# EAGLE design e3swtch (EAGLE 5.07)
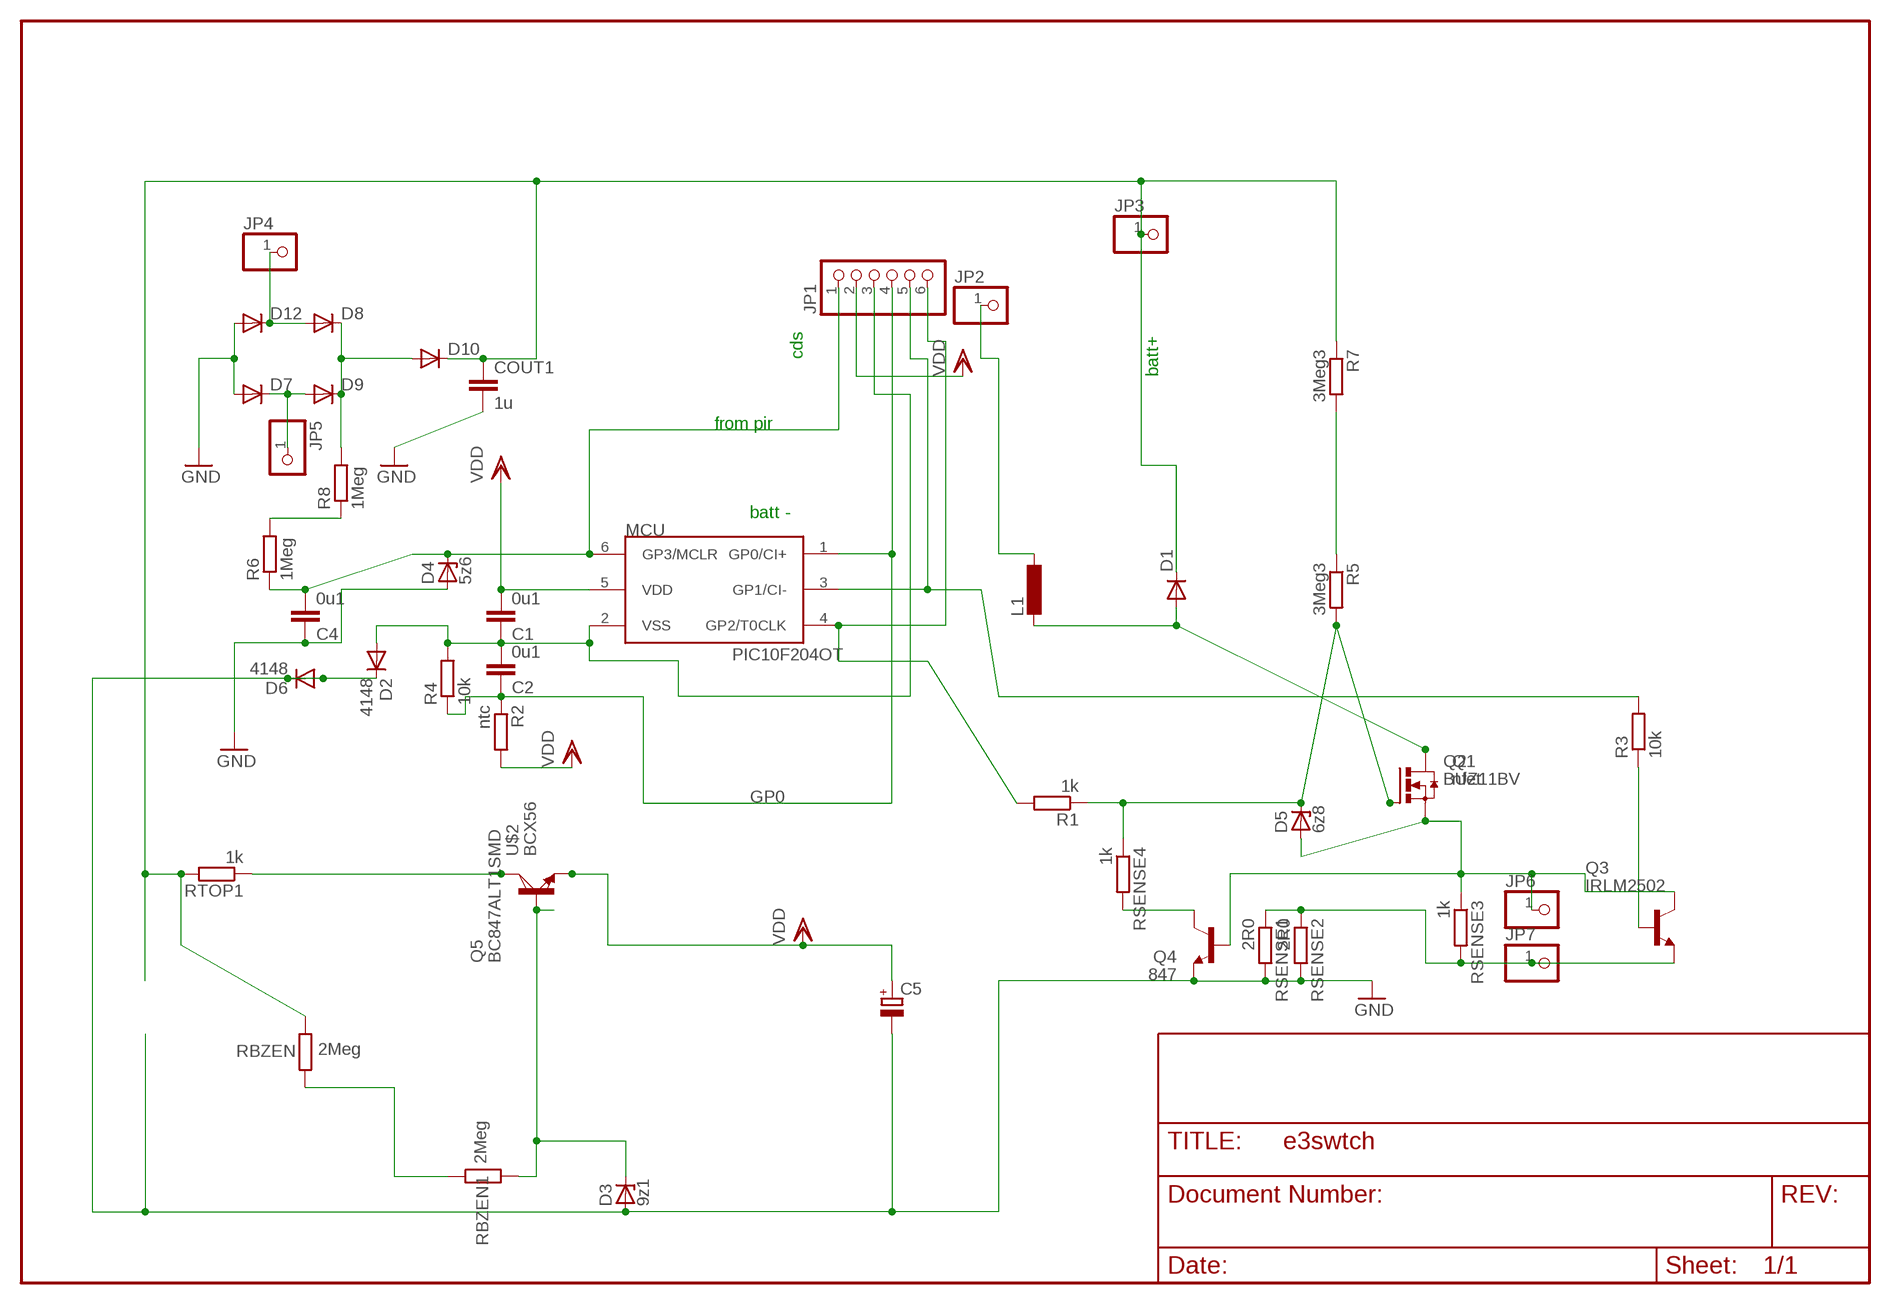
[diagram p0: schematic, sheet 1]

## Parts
C1  0u1  C-EUC0805  [C0805]
C2  0u1  C-EUC0805  [C0805]
C4  0u1  C-EUC1206  [C1206]
C5  CPOL-EUSANYO_SMD_C6  [SANYO-OSCON_SMD_C6]
COUT1  1u  C-EU075-032X103  [C075-032X103]
D1  DIODE-SMC  [SMC]
D2  4148  1N4148MINIMELF  [MINIMELF]
D3  9z1  ZENER-DIODESOD80C  [SOD80C]
D4  5z6  ZENER-DIODESOD80C  [SOD80C]
D5  6z8  ZENER-DIODESOD80C  [SOD80C]
D6  4148  1N4148MINIMELF  [MINIMELF]
D7  DIODE-DO214AA  [DO214AA]
D8  DIODE-SOD80C  [SOD80C]
D9  DIODE-SOD80C  [SOD80C]
D10  DIODE-SOD80C  [SOD80C]
D12  DIODE-DO214AA  [DO214AA]
JP1  PINHD-1X6  [1X06BOX]
JP2  PINHD-1X11MM6  [1X1MM8]
JP3  PINHD-1X11MM6  [1X1MM8]
JP4  PINHD-1X11MM6  [1X1MM8]
JP5  PINHD-1X11MM6  [1X1MM8]
JP6  PINHD-1X1INCH  [1X01]
JP7  PINHD-1X1INCH  [1X01]
L1  L-EUPIS2816  [PIS2816]
MCU  PIC10F204OT  [SOT23-6]
Q1  nfet  N-HEXFET_DPAK-  [TO252]
Q2  BUZ11BV  [TO220BV]
Q3  IRLM2502  BC847ALT1SMD  [SOT23]
Q4  847  BC847ASMD  [SOT23]
Q5  BC847ALT1SMD  [SOT23]
R1  1k  R-EU_R0805  [R0805]
R2  ntc  R-EU_0204/5  [0204/5]
R3  10k  R-EU_R0805  [R0805]
R4  10k  R-EU_R0805  [R0805]
R5  3Meg3  R-EU_R1206  [R1206]
R6  1Meg  R-EU_R1206  [R1206]
R7  3Meg3  R-EU_R1206  [R1206]
R8  1Meg  R-EU_R1206  [R1206]
RBZEN  2Meg  R-EU_R1206  [R1206]
RBZEN1  2Meg  R-EU_R1206  [R1206]
RSENSE1  2R0  R-EU_R1210  [R1210]
RSENSE2  2R0  R-EU_R1206  [R1206]
RSENSE3  1k  R-EU_R1206  [R1206]
RSENSE4  1k  R-EU_0204/5  [0204/5]
RTOP1  1k  R-EU_R1206  [R1206]
U$2  BCX56  [SOT223]

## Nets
AC1: D8.A D12.C JP4.1
AC2: D7.C D9.A JP5.1
BSW1: JP7.1 Q3.2(E) RSENSE1.1 RSENSE2.1 RSENSE3.2
C: Q5.3(C) RTOP1.1 U$2.2(C)
CB: D3.C Q5.1(B) RBZEN1.2 U$2.1(B)
GND: C4.1 C5.- COUT1.2 D2.C D3.A D4.A D6.A D6.C D7.A D12.A Q4.2(E) RSENSE1.2 RSENSE2.2
GP0: C2.1 JP1.4 MCU.1(GP0/CI+) R2.1 R4.1
HOT: D1.A L1.2 Q1.3(D) Q2.D
LED-: JP2.1 L1.1
N$1: D5.C Q1.1(G) Q2.G R1.1 R5.2 RSENSE4.1
N$3: C4.2 D4.C JP1.1 MCU.6(GP3/MCLR) R6.1
N$4: R5.1 R7.2
N$5: Q3.1(B) R3.1
N$6: RBZEN1.1 RBZEN.2
N$7: Q4.3(C) RSENSE4.2
N$9: R6.2 R8.1
N$12: JP1.5 MCU.3(GP1/CI-) R3.2
N$14: JP1.6 MCU.4(GP2/T0CLK) R1.2
N$16: D8.C D9.C D10.A R8.2
S: D5.A JP6.1 Q1.2(S) Q2.S Q3.3(C) Q4.1(B) RSENSE3.1
VDD: C1.2 C5.+ JP1.2 MCU.5(VDD) Q5.2(E) R2.2 U$2.3(E)
VPLUS: COUT1.1 D1.C D10.C JP3.1 R7.1 RBZEN.1 RTOP1.2
VSS: C1.1 C2.2 D2.A JP1.3 MCU.2(VSS) R4.2

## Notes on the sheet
- cds
- batt+
- from pir
- batt -

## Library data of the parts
C1 C2 C4 COUT1 = rcl:C-EU: CAPACITOR, European symbol
C5 = rcl-2:CPOL-EU: POLARIZED CAPACITOR, European symbol
D1 = diode-1:DIODE-: DIODE
D2 D6 = diode-1:1N4148: DIODE
D3-D5 = diode:ZENER-DIODE: Z-Diode
D7-D10 D12 = diode:DIODE-: DIODE
JP1 = pinhead:PINHD-1X6: PIN HEADER
JP2-JP5 = pinhead:PINHD-1X1: PIN HEADER
JP6 JP7 = pinhead(2):PINHD-1X1: PIN HEADER
L1 = rcl:L-EU: INDUCTOR, European symbol
MCU = microchip-3:PIC10F2*: uPC nW 0,25/0,5k Program Flash memory Comparator
Q1 = transistor-power:N-HEXFET_?-*: HEXFET® Power MOSFET
Q2 = transistor-power:BUZ11: N-CHANNEL MOS FET
Q3-Q5 = transistor-npn:BC847*: NPN Transistor
R1-R3 R5 R7 RBZEN RBZEN1 RSENSE1-RSENSE4 RTOP1 = rcl:R-EU_: RESISTOR, European symbol
R4 R6 R8 = rcl-2:R-EU_: RESISTOR, European symbol
U$2 = transistor-power:BCX56

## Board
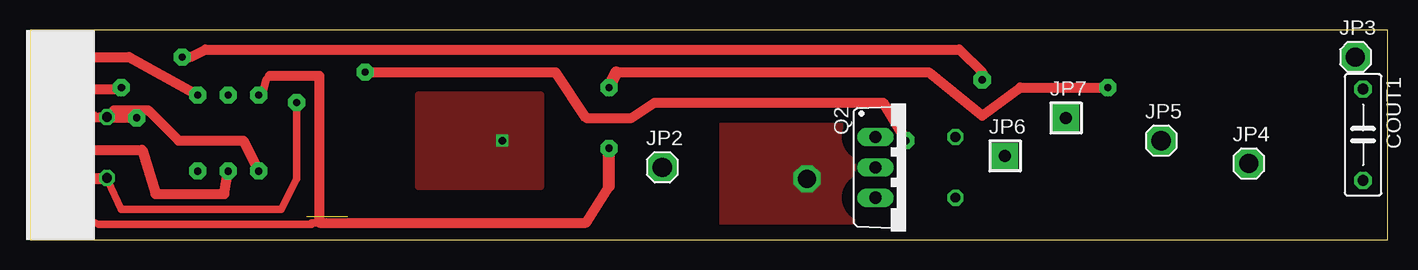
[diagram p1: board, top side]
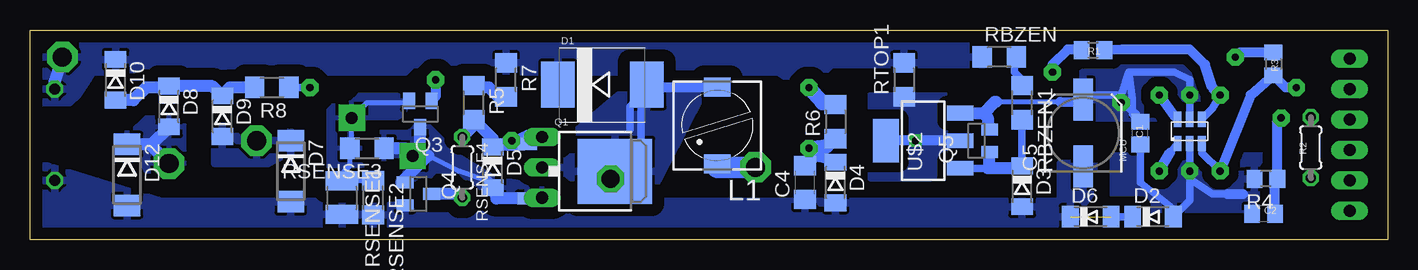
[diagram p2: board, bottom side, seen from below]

Size 113.19 x 17.5 mm. Coordinates in mm from the lower left corner, seen from the top.
Outline: 0,0 113.19,0 113.19,17.5 0,17.5 0,0
Copper layers (1*16): Top 0.035mm / dielectric 1.5mm / Bottom 0.035mm
Design rules "default *": minimum track width 10mil, minimum drill 24mil, track to track 8mil, track to pad 8mil, pad to pad 8mil, via to via 8mil, smd to smd 8mil, copper to edge 20mil, drill to drill 8mil, minimum pad ring 10mil, minimum via ring 8mil, stop-mask expansion 4mil, vias tented up to drill 0mil, thermal gap 10mil

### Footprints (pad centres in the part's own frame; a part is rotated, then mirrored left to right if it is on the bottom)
C0805 = smd 1.3 x 1.5: 1 -0.95,0; 2 0.95,0
C1206 = smd 1.6 x 1.8: 1 -1.4,0; 2 1.4,0
SANYO-OSCON_SMD_C6 = smd 3.5 x 1.6: + 2.8,0; - -2.8,0
C075-032X103 = drill 0.914 octagon: 1 -3.81,0; 2 3.81,0
SMC = smd 2.8 x 3.8: A 3.7,0; C -3.7,0
MINIMELF = smd 1.4 x 1.8: A 1.7,0; C -1.7,0
SOD80C = smd 1.4 x 1.8: A 1.7,0; C -1.7,0
DO214AA = smd 1.8 x 2.2: A 2.55,0; C -2.55,0
1X06BOX = drill 1.016 long: 1 -6.35,0; 2 -3.81,0; 3 -1.27,0; 4 1.27,0; 5 3.81,0; 6 6.35,0
1X1MM8 = drill 1.6 pad 2.54 octagon: 1 0,0
1X01 = drill 1 pad 2.184 square: 1 0,0
PIS2816 = smd 2.2 x 1.6: 1 0,3.2; 2 0,-3.2
SOT23-6 = smd 0.635 x 1.27: 1 -1.016,-1.016; 2 0,-1.016; 3 1.016,-1.016; 4 1.016,1.016; 5 0,1.016; 6 -1.016,1.016
TO252 = smd 1 x 1.6: 1 -2.28,-3.53; 2 2.28,-3.53 | smd 5.4 x 6.2: 3 0,3.77
TO220BV = drill 1.016 long: D 0,-2.54; G -2.54,-2.54; S 2.54,-2.54
SOT23 = smd 1 x 1.4: 1 -0.95,-1.1; 2 0.95,-1.1; 3 0,1.1
R0805 = smd 1.3 x 1.5: 1 -0.95,0; 2 0.95,0
0204/5 = drill 0.813 octagon: 1 -2.54,0; 2 2.54,0
R1206 = smd 1.6 x 1.803: 1 -1.422,0; 2 1.422,0
R1210 = smd 1.6 x 2.7: 1 -1.4,0; 2 1.4,0
SOT223 = smd 1.219 x 2.235: 1 -2.311,-3.099; 2 0,-3.099; 3 2.311,-3.099 | smd 3.6 x 2.2: 4 0,3.099

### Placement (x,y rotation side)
C1  20.64,8.89 90 bottom
C2  10.35,2.16 180 bottom
C4  48.58,4.76 90 bottom
C5  25.4,8.89 90 bottom
COUT1  111.12,8.75 270 top
D1  65.47,12.94 0 bottom
D2  19.57,1.91 0 bottom
D3  30.48,4.45 270 bottom
D4  46.04,4.76 270 bottom
D5  74.61,6.03 270 bottom
D6  24.77,1.91 0 bottom
D7  91.44,5.71 270 bottom
D8  101.6,11.11 270 bottom
D9  97.16,10.29 270 bottom
D10  106.05,13.34 270 bottom
D12  105.09,5.4 270 bottom
JP1  3.17,8.75 90 top
JP2  52.7,6.03 0 top
JP3  110.49,15.24 0 top
JP4  101.6,6.35 0 top
JP5  94.3,8.26 0 top
JP6  81.28,6.99 0 top
JP7  86.36,10.16 0 top
L1  55.88,9.53 180 bottom
MCU  16.51,9.03 0 bottom
Q1  68.2,5.7 270 bottom
Q2  73.03,6.03 270 top
Q3  80.64,10.48 180 bottom
Q4  80.81,3.81 270 bottom
Q5  34.29,8.26 90 bottom
R1  24.57,15.81 0 bottom
R2  6.41,7.68 270 bottom
R3  9.53,14.67 270 bottom
R4  10.16,5.08 180 bottom
R5  76.2,11.43 270 bottom
R6  46.04,9.84 90 bottom
R7  73.5,13.34 270 bottom
R8  93.03,12.7 180 bottom
RBZEN  32.38,15.24 0 bottom
RBZEN1  30.48,11.43 270 bottom
RSENSE1  87.19,3.49 270 bottom
RSENSE2  84.58,3.49 270 bottom
RSENSE3  85.09,7.62 180 bottom
RSENSE4  77.15,6.03 270 bottom
RTOP1  40.32,13.34 90 bottom
U$2  38.73,8.26 90 bottom

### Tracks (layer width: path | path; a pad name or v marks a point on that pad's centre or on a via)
AC1
  Bottom 1.016: 103.2,7.95 D12.C | JP4.1 103.2,7.95 | 103.2,7.95 103.06,7.95 D8.A
  pour Bottom (isolate 0.813, rank 2): 100.97,10.16 103.5,10.16 104.78,8.89 105.41,8.89 104.78,8.26 103.5,5.71 100.33,5.71 100.33,9.53
AC2
  pour Bottom (isolate 0.813): 97.79,9.53 90.81,8.89 90.81,7.62 93.34,6.35 97.79,6.35
BSW1
  Bottom 0.406: RSENSE1.1 84.92,4.89 RSENSE2.1 | RSENSE1.1 87.44,4.89 | RSENSE1.1 87,5.08 87,5.71 86.51,6.2 RSENSE3.2 86.36,7.77 JP7.1 85.09,11.43 81.74,11.43 Q3.2
  pour Bottom (isolate 0.813, rank 2): 88.27,5.71 88.27,10.79 87.63,11.43 86.36,11.43 85.72,12.06 82.55,12.06 81.92,11.43 81.92,10.79 82.55,10.16 85.09,10.16 85.72,9.53 85.72,6.35 84.45,5.08 84.45,4.45
C  (via drill 0.6)
  Bottom 0.813: 41.91,8.26 v39.37,8.26 Q5.3
  Bottom 1.016: Q5.3 U$2.2
  pour Top (isolate 0.61, rank 4): 32.38,12.06 42.55,12.06 42.55,4.45 32.38,4.45
  pour Bottom (isolate 0.813, no thermals): 36.83,12.06 43.18,12.06 43.18,5.08 38.1,5.08 36.83,5.71
CB
  Bottom 0.61: RBZEN1.2 D3.C 30.65,5.97 | 33.33,5.94 U$2.1
  Bottom 1.016: 33.02,5.94 30.68,5.94 D3.C | 33.02,5.94 33.33,5.94 | Q5.1 33.19,6.11 33.02,5.94
GND  (1 unrouted)
  Bottom 0.61: D2.C D6.A
  pour Bottom (isolate 1.016, rank 4): 27.3,3.17 102.23,3.17 112.39,6.35 112.39,0.64 25.72,0.64 25.72,2.54 24.77,3.81 24.13,6.35 27.3,6.35
GP0  (via drill 0.6 pad 1.42)
  Top 0.61: 5.33,10.41 5.08,10.16 3.31,10.16 JP1.4
  Top 0.813: v19.05,5.71 17.78,8.26 12.38,8.26 9.84,10.79 6.99,10.79 6.99,10.54 R2.1 | 5.08,10.16 5.14,10.16 R2.1 | v8.89,10.16 6.48,10.16 R2.1
  Bottom 0.61: 18.16,7.24 MCU.1
  Bottom 0.813: v19.05,5.71 18.16,7.24 | C2.1 9.4,4.89 R4.1 9.21,9.84 v8.89,10.16
HOT  (via drill 1.5 pad 1.42)
  Bottom 0.61: 62.23,11.43 62.23,6.35 64.43,6.35 Q1.3 | 62.23,11.43 62.23,12.13 D1.A 60.5,12.72 | 63.18,9.21 63.18,11.11 62.87,11.43 62.23,11.43
  Bottom 0.813: 60.5,12.72 L1.2
  other vias: 64.77,5.08
  pour Bottom (isolate 1.27): 57.15,12.06 64.14,12.06 68.58,8.26 69.22,8.26 69.22,3.49 61.59,3.49
  pour Top (isolate 1.27): 57.78,10.79 66.67,10.79 68.58,8.26 68.58,1.27 57.78,1.27
LED-
  Bottom 0.61: 55.88,6.03 L1.1
  Bottom 1.778: JP2.1 55.88,6.03
N$1  (via drill 0.6 pad 1.42)
  Top 0.813: v73.03,8.26 71.12,11.43 52.07,11.43 50.16,10.16 46.35,10.16 43.81,13.97 v27.94,13.97
  Bottom 0.406: D5.C 74.61,8.42 | R5.2 76.2,9.53
  Bottom 0.61: D5.C 71.99,7.73 Q1.1 71.73,8.87 v73.03,8.26 71.75,8.57 Q2.G | R1.1 25.59,15.88
  Bottom 0.813: v27.94,13.97 27.94,14.61 26.67,15.88 25.59,15.88
  Bottom 1.016: 74.61,8.42 R5.2 | 76.2,9.53 RSENSE4.1
N$3  (via drill 0.6 pad 1.42)
  Top 0.61: JP1.1 5.71,1.27 23.5,1.27 23.5,1.4 24.13,1.4 | 20,13.65 19.68,13.34 19.37,12.06 v19.05,12.06
  Top 0.813: 20,13.65 24.13,13.65 24.13,1.4 46.35,1.4 48.26,4.45
  Top 1.016: 48.26,4.45 v48.26,7.62
  Bottom 0.61: 17.78,10.3 MCU.6 | C4.2 47.61,6.8 D4.C 47.1,7.1 v48.26,7.62 | 46.83,7.79 R6.1
  Bottom 0.813: v19.05,12.06 17.78,10.3
  Bottom 1.27: v48.26,7.62 46.83,7.79
N$4
  Bottom 0.406: R7.2 74.14,11.91 | 76.05,12.7 R5.1
  Bottom 1.016: 74.14,11.91 74.93,12.7 76.05,12.7
N$5  (via drill 0.6 pad 1.42)
  Top 0.813: v12.7,15.24 13.34,15.24 14.61,15.88 77.47,15.88 79.38,13.97 v79.38,13.34
  Bottom 0.406: 79.38,11.9 Q3.1
  Bottom 0.813: R3.1 12.32,15.62 v12.7,15.24 | v79.38,13.34 79.38,11.9
N$6
  Bottom 0.61: RBZEN1.1 30.48,13.34 31.11,13.97 31.11,15.09 RBZEN.2
N$7
  Bottom 0.406: RSENSE4.2 77.62,3.81
  Bottom 1.016: 77.62,3.81 Q4.3
N$9  (via drill 0.6 pad 1.42)
  Top 0.813: 48.9,13.97 74.93,13.97 79.38,10.34 82.55,12.7 v89.85,12.7
  Top 1.016: v48.26,12.7 48.9,13.97
  Bottom 0.61: R6.2 47.14,11.43 | v89.85,12.7 R8.1
  Bottom 1.27: 47.14,11.43 v48.26,12.7
N$12  (via drill 0.6 pad 1.42)
  Top 0.406: 7.48,12.56 v7.62,12.7
  Top 0.813: JP1.5 7.48,12.56
  Bottom 0.406: 15.49,7.24 MCU.3
  Bottom 0.61: v13.97,5.71 15.49,7.24
  Bottom 0.813: v7.62,12.7 8.51,12.7 R3.2 11.43,12.06 v13.97,5.71
N$14  (via drill 0.6 pad 1.42)
  Top 0.813: v13.97,12.06 8.26,15.24 3.31,15.24 JP1.6
  Bottom 0.61: v13.97,12.06 14.61,10.94 MCU.4
  Bottom 0.813: R1.2 22.16,15.88 16.51,15.88 15.24,14.61 14.61,12.7 v13.97,12.06
N$16
  Bottom 1.016: D10.A 104.57,11.63 103.5,12.7 101.71,12.7 D8.C 97.97,12.81 D9.C 97.16,12.06 96.52,12.7 R8.2
S
  Bottom 0.406: D5.A 74.61,4.76 74.93,5.08 75.56,5.08 77.47,5.71 80,7.01 80.64,7.45 | 82.24,4.76 Q4.1
  Bottom 0.61: Q2.S 71.73,3.49 Q1.2 | 74.3,3.42 74.3,3.81 74.61,3.81 D5.A
  Bottom 1.016: Q1.2 74.3,3.42 | 80.64,7.45 Q3.3 | 80,7.01 82.24,4.76 | RSENSE3.1 81.92,7.62 JP6.1
  pour Bottom (isolate 0.813, rank 3): 70.48,4.45 74.3,5.08 77.47,6.99 80.01,9.53 83.82,9.53 83.82,6.35 82.55,5.08 80.01,5.08 79.38,5.71 77.47,5.71 75.56,3.81 70.48,3.17
VDD  (via drill 0.6 pad 1.42)
  Top 0.61: JP1.2 6.49,4.94 7.62,2.54 20.95,2.54 22.23,5.08 v22.23,11.43
  Top 0.813: R2.2 3.38,5.14 JP1.2
  Bottom 0.406: 27.3,11.49 32.65,11.49
  Bottom 0.61: 34.34,10.54 U$2.3 | 26.04,11.43 C5.+ 25.4,12.06 22.23,12.06 21.59,13.97 | MCU.5 v16.51,12.06 16.51,13.34 17.78,13.97 21.59,13.97 | 21.59,13.97 21.27,11.75 21.27,10.48 20.95,10.16 C1.2 20.96,10.48 v22.23,11.43
  Bottom 0.813: 26.04,11.43 27.3,11.49
  Bottom 1.016: 33.72,10.54 34.34,10.54 | 33.72,10.54 33.34,10.16 33.34,9.35 Q5.2 | 32.65,11.49 32.77,11.49 33.72,10.54
  pour Bottom (isolate 0.813, rank 2): 24.77,10.16 13.34,10.16 13.34,13.97 13.97,14.61 24.77,14.61 26.04,13.34
VPLUS
  Bottom 1.016: JP3.1 111.12,13.2 COUT1.1
  pour Bottom (isolate 1.016, rank 3): 112.71,15.88 112.39,13.65 112.39,11.43 109.86,11.43 109.22,12.06 107.95,13.97 81.92,13.97 81.28,14.61 74.3,14.61 73.66,13.97 50.8,13.97 48.9,12.7 48.26,12.7 46.35,14.61 33.66,14.61 34.92,16.51 111.12,16.51
VSS  (via drill 0.6 pad 1.42)
  Top 0.813: JP1.3 9.35,7.48 10.48,3.81 16.19,3.81 v16.51,5.71
  Bottom 0.61: C1.1 20.64,4.76 17.51,2.27 | 17.51,2.27 16.51,3.27 16.51,5.08 | 17.51,2.27 D2.A | 16.51,5.08 v16.51,5.71 MCU.2 | 16.51,5.08 14.61,3.81 13.34,3.81
  Bottom 0.813: 13.34,3.81 12.06,3.81
  pour Bottom (isolate 0.813): 9.53,6.99 22.86,6.99 22.86,2.54 9.53,2.54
